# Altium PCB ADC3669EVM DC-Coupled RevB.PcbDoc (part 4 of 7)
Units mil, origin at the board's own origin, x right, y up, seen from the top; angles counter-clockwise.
Board outline 5000 x 2716.54 mil, 12 copper layers (Top Layer, L2 GND, L3 SIG, L4 GND, L5 PWR, L6 GND, L7 GND, L8 PWR, L9 GND, L10 PWR, L11 GND, Bottom Layer), stack 61 mil thick; 546 components, 341 nets, 2088 pads, 1256 vias.
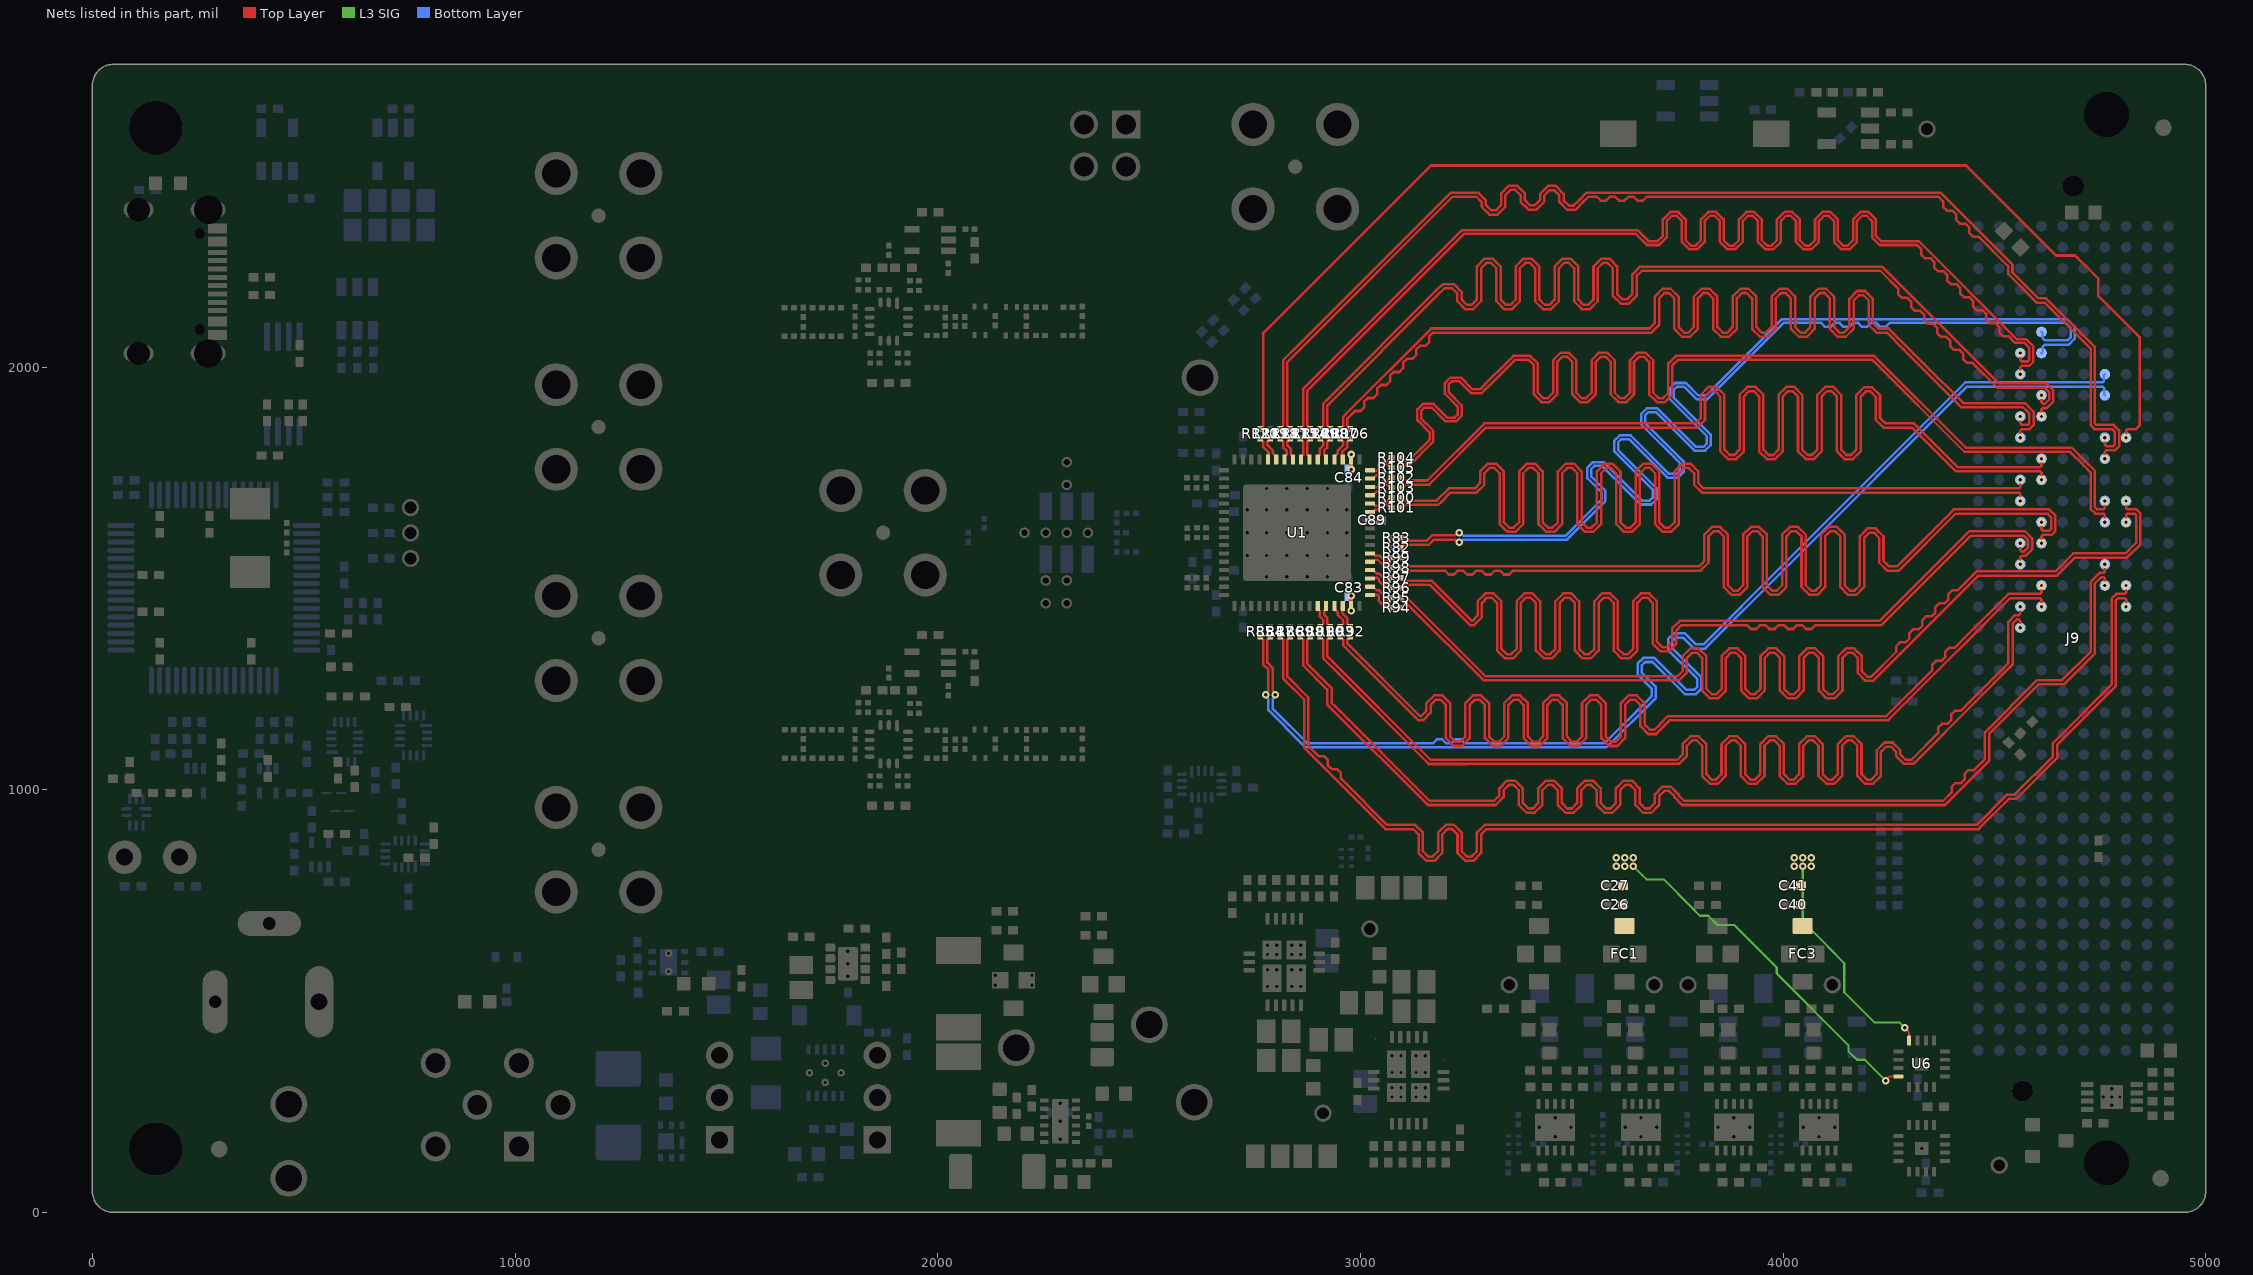
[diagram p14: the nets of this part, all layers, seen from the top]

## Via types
v1: diameter 18, hole 8, Top Layer to Bottom Layer, tented both sides, 1256 vias

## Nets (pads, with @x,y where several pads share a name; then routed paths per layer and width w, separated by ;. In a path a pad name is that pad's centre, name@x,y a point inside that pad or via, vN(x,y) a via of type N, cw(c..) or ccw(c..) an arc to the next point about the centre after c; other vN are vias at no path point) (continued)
DOUT3_n: R91.1 U1.43 | length 58.2
  Top Layer w6: U1.43@2899.21,1435.04 2899.21,1428.15 2904.06,1423.31 2904.06,1410.09 2912.06,1402.09 2912.06,1392.64 R91.1@2908.54,1389.13 ; R91.1@2905.21,1385.04 2905.21,1385.83 R91.1@2908.51,1389.13
DOUT3_p: R90.1 U1.44 | length 58.2
  Top Layer w6: U1.44@2918.9,1435.04 2918.9,1428.15 2914.06,1423.31 2914.06,1414.23 2922.06,1406.23 2922.06,1392.64 R90.1@2925.57,1389.13 ; R90.1@2925.6,1389.13 2928.9,1385.83 R90.1@2928.87,1385.04
DOUT4_n: R93.1 U1.45 | length 61.5
  Top Layer w6: U1.45@2938.58,1435.04 2938.58,1428.15 2946.81,1419.92 2946.81,1413.74 2959.43,1401.13 2959.43,1392.64 2955.91,1389.13 2952.58,1385.83 R93.1@2952.58,1385.04
DOUT4_p: R92.1 U1.46 | length 58.7
  Top Layer w6: U1.46@2958.27,1435.04 2956.81,1433.59 2956.81,1417.88 2969.43,1405.27 2969.43,1392.64 2972.94,1389.13 2976.27,1385.83 R92.1@2976.27,1385.04
DOUT5_n: R95.1 U1.50 | length 73.2
  Top Layer w6: U1.50@3023.23,1480.32 3030.12,1480.32 3038.62,1471.81 3044.26,1471.81 3053.63,1462.44 3053.63,1450.99 3057.14,1447.47 3065.63,1447.47 R95.1@3069.14,1450.99 ; R95.1@3069.14,1451.02 3072.44,1454.32 R95.1@3073.23,1454.32
DOUT5_p: R94.1 U1.49 | length 70.1
  Top Layer w6: U1.49@3023.23,1460.63 3024.41,1461.81 3040.11,1461.81 3043.63,1458.3 3043.63,1446.85 3053,1437.47 3065.63,1437.47 3069.14,1433.96 3072.44,1430.63 R94.1@3073.23,1430.63
DOUT6_n: R97.1 U1.52 | length 65.2
  Top Layer w6: U1.52@3023.23,1519.69 3030.12,1519.69 3038.62,1511.18 3044.26,1511.18 3053.63,1501.81 3053.63,1498.36 3057.14,1494.84 3065.63,1494.84 R97.1@3069.14,1498.36 ; R97.1@3069.14,1498.39 3072.44,1501.69 R97.1@3073.23,1501.69
DOUT6_p: R96.1 U1.51 | length 62.1
  Top Layer w6: U1.51@3023.23,1500 3024.41,1501.18 3040.11,1501.18 3043.63,1497.67 3043.63,1494.22 3053,1484.84 3065.63,1484.84 R96.1@3069.14,1481.33 ; R96.1@3069.14,1481.3 3072.44,1478 R96.1@3073.23,1478
DOUT7_n: R99.1 U1.54 | length 59.8
  Top Layer w6: U1.54@3023.23,1559.06 3030.12,1559.06 3034.96,1554.21 3045.14,1554.21 3057.14,1542.21 3065.63,1542.21 3069.14,1545.73 3072.44,1549.06 R99.1@3073.23,1549.06
DOUT7_p: R98.1 U1.53 | length 59.8
  Top Layer w6: U1.53@3023.23,1539.37 3030.12,1539.37 3034.96,1544.21 3041,1544.21 3053,1532.21 3065.63,1532.21 3069.14,1528.7 3072.44,1525.37 R98.1@3073.23,1525.37
DOUT8_n: R101.1 U1.59 | length 59.8
  Top Layer w6: U1.59@3023.23,1657.48 3030.12,1657.48 3034.96,1662.32 3045.14,1662.32 3057.14,1674.32 3065.63,1674.32 3069.14,1670.81 3072.44,1667.48 R101.1@3073.23,1667.48
DOUT8_p: R100.1 U1.60 | length 59.8
  Top Layer w6: U1.60@3023.23,1677.17 3030.12,1677.17 3034.96,1672.32 3041,1672.32 3053,1684.32 3065.63,1684.32 R100.1@3069.14,1687.84 ; R100.1@3069.14,1687.87 3072.44,1691.17 R100.1@3073.23,1691.17
DOUT9_n: R103.1 U1.61 | length 65.2
  Top Layer w6: U1.61@3023.23,1696.85 3030.12,1696.85 3038.62,1705.36 3044.26,1705.36 3053.63,1714.73 3053.63,1718.18 3057.14,1721.7 3065.63,1721.7 R103.1@3069.14,1718.18 ; R103.1@3069.14,1718.15 3072.44,1714.85 R103.1@3073.23,1714.85
DOUT9_p: R102.1 U1.62 | length 62.1
  Top Layer w6: U1.62@3023.23,1716.54 3024.41,1715.36 3040.11,1715.36 3043.63,1718.87 3043.63,1722.32 3053,1731.7 3065.63,1731.7 R102.1@3069.14,1735.21 ; R102.1@3069.14,1735.24 3072.44,1738.54 R102.1@3073.23,1738.54
DOUT10_n: R105.1 U1.63 | length 73.2
  Top Layer w6: U1.63@3023.23,1736.22 3030.12,1736.22 3038.62,1744.73 3044.26,1744.73 3053.63,1754.1 3053.63,1765.55 3057.14,1769.07 3065.63,1769.07 3069.14,1765.55 3072.44,1762.22 R105.1@3073.23,1762.22
DOUT10_p: R104.1 U1.64 | length 70.1
  Top Layer w6: U1.64@3023.23,1755.91 3024.41,1754.73 3040.11,1754.73 3043.63,1758.24 3043.63,1769.69 3053,1779.07 3065.63,1779.07 3069.14,1782.58 3072.44,1785.91 R104.1@3073.23,1785.91
DOUT11_n: R107.1 U1.4 | length 61.5
  Top Layer w6: U1.4@2938.58,1781.5 2938.58,1788.39 2946.81,1796.62 2946.81,1802.8 2959.43,1815.41 2959.43,1823.9 2955.91,1827.41 2952.58,1830.71 R107.1@2952.58,1831.5
DOUT11_p: R106.1 U1.3 | length 58.7
  Top Layer w6: U1.3@2958.27,1781.5 2956.81,1782.95 2956.81,1798.66 2969.43,1811.27 2969.43,1823.9 2972.94,1827.41 2976.27,1830.71 R106.1@2976.27,1831.5
DOUT12_n: R109.1 U1.6 | length 58.2
  Top Layer w6: U1.6@2899.21,1781.5 2899.21,1788.39 2904.06,1793.23 2904.06,1806.45 2912.06,1814.45 2912.06,1823.9 R109.1@2908.54,1827.41 ; R109.1@2905.21,1831.5 2905.21,1830.71 R109.1@2908.51,1827.41
DOUT12_p: R108.1 U1.5 | length 58.2
  Top Layer w6: U1.5@2918.9,1781.5 2918.9,1788.39 2914.06,1793.23 2914.06,1802.31 2922.06,1810.31 2922.06,1823.9 R108.1@2925.57,1827.41 ; R108.1@2925.6,1827.41 2928.9,1830.71 R108.1@2928.9,1831.5
DOUT13_n: R115.1 U1.8 | length 54.9
  Top Layer w6: R115.1@2857.84,1831.5 2857.84,1830.71 2861.14,1827.41 2864.69,1823.9 2864.69,1793.23 2859.84,1788.39 U1.8@2859.84,1781.5
DOUT13_p: R114.1 U1.7 | length 54.9
  Top Layer w6: R114.1@2878.2,1827.41 2874.69,1823.9 2874.69,1793.23 2879.53,1788.39 U1.7@2879.53,1781.5 ; R114.1@2878.23,1827.41 2881.53,1830.71 R114.1@2881.53,1831.5
DOUT14_n: R118.1 U1.10 | length 58.2
  Top Layer w6: R118.1@2810.47,1831.5 2810.47,1830.71 R118.1@2813.77,1827.41 ; R118.1@2813.8,1827.41 2817.32,1823.9 2817.32,1810.31 2825.32,1802.31 2825.32,1793.23 2820.47,1788.39 U1.10@2820.47,1781.5
DOUT14_p: R117.1 U1.9 | length 58.2
  Top Layer w6: R117.1@2834.16,1831.5 2834.16,1830.71 2830.86,1827.41 2827.32,1823.9 2827.32,1814.45 2835.32,1806.45 2835.32,1793.23 2840.16,1788.39 U1.9@2840.16,1781.5
DOUT15_n: R120.1 U1.12 | length 58.7
  Top Layer w6: R120.1@2763.1,1831.5 2763.1,1830.71 R120.1@2766.4,1827.41 ; R120.1@2766.43,1827.41 2769.95,1823.9 2769.95,1811.27 2782.56,1798.66 2782.56,1782.95 U1.12@2781.1,1781.5
DOUT15_p: R119.1 U1.11 | length 61.5
  Top Layer w6: R119.1@2783.46,1827.41 2779.95,1823.9 2779.95,1815.41 2792.56,1802.8 2792.56,1796.62 2800.79,1788.39 U1.11@2800.79,1781.5 ; R119.1@2783.49,1827.41 2786.79,1830.71 R119.1@2786.79,1831.5
DVDD12: C26.2 C27.2 C83.2 C84.2 FC1.3 U1.2 U1.47 U6.8 | length 929.9
  Top Layer w5: v1(4242.68,311.92) 4252.68,321.92 U6.8@4272.68,321.92
  Top Layer w9.5: v1(2977.95,1423.23) U1.47@2977.95,1435.04 v1(2977.95,1458.85) ; v1(2977.95,1757.69) U1.2@2977.95,1781.5 v1(2977.95,1793.31)
  L3 SIG w5: v1(3645.19,819.32) 3666.42,798.09 3667.04,798.09 3677.13,788 3717.75,788 3784.67,721.08 3784.67,720.51 3803.09,702.09 3822.96,702.09 3844.94,680.11 3884.38,680.11 3985,579.49 3985,565.36 4154.56,395.81 4154.56,381.68 4174.96,361.28 4193.32,361.28 v1(4242.68,311.92)
  other v1: 3605.19,819.32 3625.19,819.32 3605.19,839.32 3625.19,839.32 3645.19,839.32
DVDD18: C40.2 C41.2 C89.2 FC3.3 U1.58 U6.4 | length 575.5
  Top Layer w5: v1(4288.27,436.56) 4298.27,426.56 U6.4@4298.27,406.56
  Top Layer w9.5: U1.58@3023.23,1637.8 v1(3047.04,1637.8)
  L3 SIG w5: v1(4046.5,819.32) 4046.5,689.06 4105.49,630.06 4105.49,629.18 4144.8,589.87 4144.8,520.96 4216.05,449.72 4275.12,449.72 v1(4288.27,436.56)
  other v1: 4026.5,819.32 4066.5,819.32 4026.5,839.32 4046.5,839.32 4066.5,839.32
FMC_DCLK_n: J9.G7 R83.2 | length 2914
  Top Layer w6: R83.2@3095.28,1596.43 3096.06,1596.43 R83.2@3099.36,1593.13 ; R83.2@3099.36,1593.1 3102.88,1589.58 3157.53,1589.58 3169.89,1601.94 3223.99,1601.94 3230.49,1608.44 v1(3233.5,1608.44)
  Bottom Layer w6: v1(3233.5,1608.44) 3235.96,1608.44 3243.46,1600.94 3485.03,1600.94 3566.25,1682.16 3570.24,1686.15 3570.24,1703.97 3537.22,1736.99 3537.22,1762.27 3550.13,1775.17 3575.4,1775.17 3666.63,1683.95 3684.45,1683.95 3692.08,1691.59 3692.08,1709.4 3600.86,1800.63 3600.86,1825.91 3613.77,1838.81 3639.04,1838.81 3730.27,1747.59 3748.09,1747.59 3755.72,1755.22 3755.72,1773.04 3664.5,1864.27 3664.5,1889.54 3677.41,1902.45 3702.68,1902.45 3793.91,1811.23 3811.72,1811.23 3819.36,1818.86 3819.36,1836.68 3731.86,1924.19 3731.86,1949.46 3744.77,1962.37 3770.04,1962.37 3799.34,1933.07 3817.16,1933.07 3916.68,2032.59 3997.76,2113.67 4671.46,2113.67 4690.02,2095.11 4690.02,2067.27 4676.02,2053.27 4619.45,2053.27 4614.71,2048.52 4614.71,2036.56 J9.G7@4611.42,2033.27
FMC_DCLK_p: J9.G6 R82.2 | length 2914.2
  Top Layer w6: R82.2@3095.28,1572.74 3096.06,1572.74 R82.2@3099.36,1576.04 ; R82.2@3099.36,1576.07 3102.88,1579.58 3161.67,1579.58 3174.03,1591.94 3223.99,1591.94 3230.49,1585.44 v1(3233.5,1585.44)
  Bottom Layer w6: v1(3233.5,1585.44) 3236.52,1585.44 3243.02,1591.94 3488.76,1591.94 3572.62,1675.8 3579.24,1682.42 3579.24,1707.7 3546.22,1740.72 3546.22,1758.54 3553.85,1766.17 3571.67,1766.17 3662.9,1674.95 3688.17,1674.95 3701.08,1687.86 3701.08,1713.13 3609.86,1804.36 3609.86,1822.18 3617.49,1829.81 3635.31,1829.81 3726.54,1738.59 3751.81,1738.59 3764.72,1751.5 3764.72,1776.77 3673.5,1868 3673.5,1885.82 3681.13,1893.45 3698.95,1893.45 3790.18,1802.23 3815.45,1802.23 3828.36,1815.14 3828.36,1840.41 3740.86,1927.91 3740.86,1945.73 3748.49,1953.37 3766.31,1953.37 3795.61,1924.07 3820.89,1924.07 3923.04,2026.23 4001.49,2104.67 4090.33,2104.67 4099.64,2095.35 4112.09,2095.35 4121.4,2104.67 4133.85,2104.67 4143.17,2095.35 4155.61,2095.35 4164.93,2104.67 4177.38,2104.67 4186.69,2095.35 4199.14,2095.35 4208.45,2104.67 4220.9,2104.67 4230.22,2095.35 4242.66,2095.35 4251.98,2104.67 4667.73,2104.67 4681.02,2091.39 4681.02,2071 4673.29,2063.27 4619.45,2063.27 4614.71,2068.01 4614.71,2079.98 J9.G6@4611.42,2083.27
FMC_DOUT0_n: J9.D9 R85.2 | length 2922.8
  Top Layer w6: R85.2@2763.1,1362.99 2763.1,1362.21 R85.2@2766.4,1358.91 ; R85.2@2766.43,1358.91 2769.95,1355.39 2769.95,1296.6 2782.3,1284.24 2782.3,1234.28 2775.8,1227.78 v1(2775.8,1224.77)
  Bottom Layer w6: v1(2775.8,1224.77) 2775.8,1221.75 2782.3,1215.25 2782.3,1188.46 2863.3,1107.46 2870.61,1100.15 3028.89,1100.15 ; 3020.61,1100.15 3028.89,1100.15 ; J9.D9@4761.42,1933.27 4759.36,1935.33 4759.36,1950.15 4755.84,1953.67 4435.18,1953.67 4002.75,1521.25 3815.64,1334.13 3789.54,1334.13 3763.61,1360.07 3745.79,1360.07 3738.15,1352.43 3738.15,1334.61 3807.02,1265.74 3807.02,1239.63 3793.53,1226.14 3767.42,1226.14 3691.26,1302.3 3673.45,1302.3 3665.81,1294.66 3665.81,1276.84 3699.03,1243.62 3699.03,1217.52 3691.91,1210.4 3587.52,1106.01 3581.66,1100.15 3028.89,1100.15
FMC_DOUT0_p: J9.D8 R84.2 | length 2912.3
  Top Layer w6: R84.2@2783.46,1358.91 2779.95,1355.39 2779.95,1300.74 2792.3,1288.38 2792.3,1234.28 2798.8,1227.78 v1(2798.8,1224.77) ; R84.2@2783.49,1358.91 2786.79,1362.21 R84.2@2786.79,1362.99
  Bottom Layer w6: v1(2798.8,1224.77) 2798.8,1221.75 2792.3,1215.25 2792.3,1192.6 2874.75,1110.15 3014.41,1110.15 3128.3,1110.15 3171.83,1110.15 3181.14,1119.47 3193.59,1119.47 3202.9,1110.15 3215.35,1110.15 3224.67,1119.47 3237.11,1119.47 3246.43,1110.15 3577.51,1110.15 3684.83,1217.47 3689.03,1221.66 3689.03,1239.48 3655.81,1272.7 3655.81,1298.8 3669.3,1312.3 3695.41,1312.3 3771.57,1236.14 3789.38,1236.14 3797.02,1243.78 3797.02,1261.6 3728.15,1330.47 3728.15,1356.57 3741.64,1370.07 3767.75,1370.07 3793.68,1344.13 3811.5,1344.13 3995.68,1528.32 4431.03,1963.67 4755.44,1963.67 4758.96,1967.18 4758.96,1980.81 J9.D8@4761.42,1983.27
FMC_DOUT1_n: J9.C19 R87.2 | length 2951.2
  Top Layer w6: R87.2@2810.5,1362.99 2810.47,1362.21 R87.2@2813.77,1358.91 ; R87.2@2813.8,1358.91 2817.32,1355.39 2817.32,1263.61 2823.17,1257.75 2866.68,1214.25 2866.68,1099.6 2872.53,1093.74 3059.27,907 3073.16,907 3125.09,907 3137.69,894.4 3137.69,850.41 3156.15,831.95 3175.23,831.95 3193.69,850.41 3193.69,894.64 3206.29,907.24 3217.09,907.24 3229.69,894.64 3229.69,850.41 3248.15,831.95 3267.23,831.95 3285.69,850.41 3285.69,894.4 3298.29,907 3328.41,907 ; 3297.57,907 3328.41,907 ; v1(4811.42,1433.27) 4811.42,1449.75 4807.9,1453.27 4792.56,1453.27 4787.42,1448.12 4787.42,1245.13 4648.18,1105.89 4648.18,1074.89 4642.32,1069.04 4557.58,984.3 4551.73,978.44 4533.97,978.44 4462.52,907 3328.41,907
FMC_DOUT1_p: J9.C18 R86.2 | length 2919.3
  Top Layer w6: R86.2@2834.16,1362.99 2834.16,1362.21 2830.86,1358.91 2827.32,1355.39 2827.32,1267.75 2876.68,1218.39 2876.68,1103.74 2900.96,1079.46 2914.13,1079.46 2922.93,1070.65 2922.93,1057.48 2931.73,1048.68 2944.91,1048.68 2953.71,1039.88 2953.71,1026.7 2962.51,1017.9 3063.41,917 3073.16,917 3129.23,917 3147.69,898.54 3147.69,854.55 3160.29,841.95 3171.09,841.95 3183.69,854.55 3183.69,898.78 3202.15,917.24 3221.23,917.24 3239.69,898.78 3239.69,854.55 3252.29,841.95 3263.09,841.95 3275.69,854.55 3275.69,898.54 3294.15,917 3328.41,917 4458.38,917 4529.82,988.44 4547.58,988.44 4638.18,1079.04 4638.18,1110.03 4777.42,1249.27 4777.42,1452.26 4788.42,1463.27 4807.9,1463.27 4811.42,1466.78 v1(4811.42,1483.27)
FMC_DOUT2_n: J9.D18 R89.2 | length 2912.4
  Top Layer w6: R89.2@2857.87,1362.99 2857.9,1362.21 2861.2,1358.91 2864.74,1355.39 2864.74,1293.54 2922.06,1236.22 2922.06,1201.61 2924.98,1198.69 3159.67,964 3310.11,964 3320.18,964 3338.64,982.46 3338.64,998.86 3351.24,1011.46 3362.04,1011.46 3374.64,998.86 3374.64,964.18 3393.1,945.73 3412.18,945.73 3430.64,964.18 3430.64,998.86 3443.24,1011.46 3454.04,1011.46 3466.64,998.86 3466.64,964.18 3485.1,945.73 3504.18,945.73 3522.64,964.18 3522.64,998.86 3535.24,1011.46 3546.04,1011.46 3558.64,998.86 3558.64,964.18 3577.1,945.73 3596.18,945.73 3614.64,964.18 3614.64,998.86 3627.24,1011.46 3638.04,1011.46 3650.64,998.86 3650.64,964.18 3669.1,945.73 3688.18,945.73 3706.64,964.18 3706.64,984.98 3719.24,997.58 3730.04,997.58 3742.64,984.98 3742.64,982.46 3761.1,964 3808.97,964 4383.03,964 4487.42,1068.39 4487.42,1131.89 4604.79,1249.27 4664.55,1249.27 4670.41,1255.13 4731.56,1316.28 4737.42,1322.14 4737.42,1487.75 4752.93,1503.27 4757.9,1503.27 4761.42,1499.75 v1(4761.42,1483.27)
FMC_DOUT2_p: J9.D17 R88.2 | length 2911.3
  Top Layer w6: R88.2@2878.25,1358.91 2874.74,1355.39 2874.74,1297.68 2929.13,1243.29 2932.06,1240.36 2932.06,1205.76 2939.73,1198.09 3163.81,974 3310.11,974 3316.04,974 3328.64,986.6 3328.64,1003 3347.1,1021.46 3366.18,1021.46 3384.64,1003 3384.64,968.33 3397.24,955.73 3408.04,955.73 3420.64,968.33 3420.64,1003 3439.1,1021.46 3458.18,1021.46 3476.64,1003 3476.64,968.33 3489.24,955.73 3500.04,955.73 3512.64,968.33 3512.64,1003 3531.1,1021.46 3550.18,1021.46 3568.64,1003 3568.64,968.33 3581.24,955.73 3592.04,955.73 3604.64,968.33 3604.64,1003 3623.1,1021.46 3642.18,1021.46 3660.64,1003 3660.64,968.33 3673.24,955.73 3684.04,955.73 3696.64,968.33 3696.64,989.12 3715.1,1007.58 3734.18,1007.58 3752.64,989.12 3752.64,986.6 3765.24,974 3808.97,974 4378.89,974 4398.53,993.64 4398.53,1006.81 4407.33,1015.62 4420.5,1015.62 4429.3,1024.42 4429.3,1037.59 4438.1,1046.39 4451.28,1046.39 4477.42,1072.53 4477.42,1136.04 4600.65,1259.27 4660.41,1259.27 4727.42,1326.28 4727.42,1491.89 4748.79,1513.27 4757.9,1513.27 4761.42,1516.78 v1(4761.42,1533.27) ; R88.2@2878.28,1358.91 2881.58,1362.21 R88.2@2881.58,1362.99
FMC_DOUT3_n: J9.H20 R91.2 | length 2912.4
  Top Layer w6: R91.2@2905.21,1362.99 2905.21,1362.21 R91.2@2908.51,1358.91 ; R91.2@2908.54,1358.91 2912.06,1355.39 2912.06,1310.79 2948.93,1273.92 2949.06,1273.92 3158.99,1064 3161.89,1061.1 3161.99,1061 3250.59,1061 3250.68,1061.1 3744.02,1061.1 3754.03,1061.1 3772.43,1079.5 3772.43,1104.14 3785.03,1116.74 3795.83,1116.74 3808.43,1104.14 3808.43,1032.74 3826.83,1014.34 3845.83,1014.34 3864.23,1032.74 3864.23,1104.14 3876.83,1116.74 3887.63,1116.74 3900.23,1104.14 3900.23,1032.74 3918.63,1014.34 3937.64,1014.34 3956.04,1032.74 3956.04,1104.14 3968.64,1116.74 3979.44,1116.74 3992.04,1104.14 3992.04,1032.74 4010.44,1014.34 4029.44,1014.34 4047.84,1032.74 4047.84,1104.14 4060.44,1116.74 4071.24,1116.74 4083.84,1104.14 4083.84,1032.74 4102.25,1014.34 4121.25,1014.34 4139.65,1032.74 4139.65,1104.14 4152.25,1116.74 4163.05,1116.74 4175.65,1104.14 4175.65,1032.74 4194.05,1014.34 4213.05,1014.34 4231.46,1032.74 4231.46,1089.39 4244.06,1101.99 4254.86,1101.99 4267.46,1089.39 4267.46,1079.5 4285.86,1061.1 4296.93,1061.1 4307.96,1061.1 4310.69,1063.83 4310.83,1063.83 4455.86,1208.86 4537.14,1290.14 4543,1296 4543,1393.33 4552.93,1403.27 4557.9,1403.27 4561.42,1399.75 v1(4561.42,1383.27)
FMC_DOUT3_p: J9.H19 R90.2 | length 2924.7
  Top Layer w6: R90.2@2925.57,1358.91 2922.06,1355.39 2922.06,1314.94 3165.99,1071 3246.44,1071 3246.54,1071.1 3329.19,1071.1 3329.28,1071 ; R90.2@2925.6,1358.91 2928.9,1362.21 R90.2@2928.87,1362.99 ; 3315.99,1071 3329.28,1071 ; v1(4561.42,1433.27) 4561.42,1416.78 4557.9,1413.27 4548.79,1413.27 4533,1397.48 4533,1300.14 4419.51,1186.65 4406.33,1186.65 4397.53,1177.85 4397.53,1164.67 4388.73,1155.87 4375.56,1155.87 4366.76,1147.07 4366.76,1133.9 4303.86,1071 4296.93,1071 4289.96,1071 4277.36,1083.6 4277.36,1093.49 4258.96,1111.89 4239.95,1111.89 4221.55,1093.49 4221.55,1036.84 4208.95,1024.24 4198.15,1024.24 4185.55,1036.84 4185.55,1108.24 4167.15,1126.64 4148.15,1126.64 4129.75,1108.24 4129.75,1036.84 4117.15,1024.24 4106.35,1024.24 4093.75,1036.84 4093.75,1108.24 4075.35,1126.64 4056.34,1126.64 4037.94,1108.24 4037.94,1036.84 4025.34,1024.24 4014.54,1024.24 4001.94,1036.84 4001.94,1108.24 3983.54,1126.64 3964.54,1126.64 3946.14,1108.24 3946.14,1036.84 3933.54,1024.24 3922.74,1024.24 3910.14,1036.84 3910.14,1108.24 3891.74,1126.64 3872.73,1126.64 3854.33,1108.24 3854.33,1036.84 3841.73,1024.24 3830.93,1024.24 3818.33,1036.84 3818.33,1108.24 3799.93,1126.64 3780.93,1126.64 3762.52,1108.24 3762.52,1083.6 3749.93,1071 3744.02,1071 3329.28,1071
FMC_DOUT4_n: J9.G19 R93.2 | length 2912.4
  Top Layer w6: R93.2@2952.58,1362.99 2952.58,1362.21 2955.88,1358.91 2959.43,1355.39 2959.43,1341.75 2965.28,1335.89 3015.18,1286 3137.16,1164.02 3137.77,1164.02 3147.84,1164.02 3166.3,1182.48 3166.3,1200.83 3178.9,1213.43 3189.7,1213.43 3202.3,1200.83 3202.3,1122.02 3220.75,1103.56 3239.84,1103.56 3258.3,1122.02 3258.3,1200.83 3270.9,1213.43 3281.7,1213.43 3294.3,1200.83 3294.3,1122.02 3312.75,1103.56 3331.84,1103.56 3350.3,1122.02 3350.3,1200.83 3362.9,1213.43 3373.7,1213.43 3386.3,1200.83 3386.3,1122.02 3404.75,1103.56 3423.84,1103.56 3442.3,1122.02 3442.3,1200.83 3454.89,1213.43 3465.69,1213.43 3478.29,1200.83 3478.29,1122.02 3496.75,1103.56 3515.84,1103.56 3534.29,1122.02 3534.29,1200.83 3546.89,1213.43 3557.69,1213.43 3570.29,1200.83 3570.29,1122.02 3588.75,1103.56 3607.84,1103.56 3626.29,1122.02 3626.29,1200.83 3638.89,1213.43 3649.69,1213.43 3662.29,1200.83 3662.29,1150.47 3680.75,1132.01 3699.84,1132.01 3718.29,1150.47 3718.29,1151.42 3730.89,1164.02 3758.18,1164.02 4248.16,1164.02 4251.26,1167.12 4392,1307.86 4434,1349.86 4537.41,1453.27 4607.9,1453.27 4611.42,1449.75 v1(4611.42,1433.27)
FMC_DOUT4_p: J9.G18 R92.2 | length 2915
  Top Layer w6: R92.2@2976.27,1362.99 2976.27,1362.21 2972.97,1358.91 2969.43,1355.39 2969.43,1345.89 3137.77,1177.55 3141.3,1174.02 3143.7,1174.02 3156.3,1186.62 3156.3,1204.97 3174.75,1223.43 3193.84,1223.43 3212.3,1204.97 3212.3,1126.16 3224.9,1113.56 3235.7,1113.56 3248.3,1126.16 3248.3,1204.97 3266.75,1223.43 3285.84,1223.43 3304.3,1204.97 3304.3,1126.16 3316.9,1113.56 3327.7,1113.56 3340.3,1126.16 3340.3,1204.97 3358.75,1223.43 3377.84,1223.43 3396.3,1204.97 3396.3,1126.16 3408.9,1113.56 3419.7,1113.56 3432.3,1126.16 3432.3,1204.97 3450.75,1223.43 3469.84,1223.43 3488.29,1204.97 3488.29,1126.16 3500.89,1113.56 3511.69,1113.56 3524.29,1126.16 3524.29,1204.97 3542.75,1223.43 3561.84,1223.43 3580.29,1204.97 3580.29,1126.16 3592.89,1113.56 3603.69,1113.56 3616.29,1126.16 3616.29,1204.97 3634.75,1223.43 3653.84,1223.43 3672.29,1204.97 3672.29,1154.61 3684.89,1142.01 3695.69,1142.01 3708.29,1154.61 3708.29,1155.56 3726.75,1174.02 3758.18,1174.02 3761.72,1174.02 ; 3757.96,1174.02 3761.72,1174.02 ; v1(4611.42,1483.27) 4611.42,1466.78 4607.9,1463.27 4533.27,1463.27 4429.86,1359.86 4405.77,1335.77 4392.6,1335.77 4383.8,1326.97 4383.8,1313.8 4375,1305 4361.82,1305 4353.02,1296.2 4353.02,1283.02 4244.02,1174.02 3761.72,1174.02
FMC_DOUT5_n: J9.C15 R95.2 | length 2911
  Top Layer w6: R95.2@3095.28,1454.32 3096.06,1454.32 R95.2@3099.36,1451.02 ; R95.2@3099.36,1450.99 3102.88,1447.47 3116.68,1447.47 3295.48,1268.67 3744.07,1268.67 3750,1268.67 3762.6,1281.27 3762.6,1316.05 3781.06,1334.51 3800.14,1334.51 3818.6,1316.05 3818.6,1238.96 3831.2,1226.36 3842,1226.36 3854.6,1238.96 3854.6,1316.05 3873.06,1334.51 3892.14,1334.51 3910.6,1316.05 3910.6,1238.96 3923.2,1226.36 3934,1226.36 3946.6,1238.96 3946.6,1316.05 3965.06,1334.51 3984.14,1334.51 4002.6,1316.05 4002.6,1238.96 4015.2,1226.36 4026,1226.36 4038.6,1238.96 4038.6,1316.05 4057.06,1334.51 4076.14,1334.51 4094.6,1316.05 4094.6,1238.96 4107.2,1226.36 4118,1226.36 4130.6,1238.96 4130.6,1316.05 4149.06,1334.51 4168.14,1334.51 4186.6,1316.05 4186.6,1280.35 4199.2,1267.75 4206.35,1267.75 4208.96,1267.75 4267.81,1326.6 4267.81,1339.77 4276.61,1348.57 4289.79,1348.57 4298.59,1357.37 4298.59,1370.55 4307.39,1379.35 4320.56,1379.35 4329.36,1388.15 4329.36,1401.32 4338.17,1410.12 4351.34,1410.12 4360.14,1418.93 4360.14,1432.1 4368.94,1440.9 4382.12,1440.9 4390.92,1449.7 4390.92,1462.88 4399.72,1471.68 4412.89,1471.68 4452.14,1510.92 4458,1516.78 4644.04,1516.78 4686.52,1559.27 4810.05,1559.27 4835.23,1584.45 4835.23,1649.75 4831.71,1653.27 4814.93,1653.27 4811.42,1649.75 v1(4811.42,1633.27)
FMC_DOUT5_p: J9.C14 R94.2 | length 2905.5
  Top Layer w6: R94.2@3095.28,1430.63 3096.06,1430.63 3099.36,1433.93 3102.88,1437.47 3112.54,1437.47 3123.1,1426.92 3288.41,1261.6 3291.34,1258.67 3744.07,1258.67 3754.14,1258.67 3772.6,1277.13 3772.6,1311.91 3785.2,1324.51 3796,1324.51 3808.6,1311.91 3808.6,1234.82 3827.06,1216.36 3846.14,1216.36 3864.6,1234.82 3864.6,1311.91 3877.2,1324.51 3888,1324.51 3900.6,1311.91 3900.6,1234.82 3919.06,1216.36 3938.14,1216.36 3956.6,1234.82 3956.6,1311.91 3969.2,1324.51 3980,1324.51 3992.6,1311.91 3992.6,1234.82 4011.06,1216.36 4030.14,1216.36 4048.6,1234.82 4048.6,1311.91 4061.2,1324.51 4072,1324.51 4084.6,1311.91 4084.6,1234.82 4103.06,1216.36 4122.14,1216.36 4140.6,1234.82 4140.6,1311.91 4153.2,1324.51 4164,1324.51 4176.6,1311.91 4176.6,1276.21 4195.06,1257.75 4206.35,1257.75 4213.11,1257.75 4362.93,1407.57 4462.14,1506.78 4648.18,1506.78 4690.66,1549.27 4814.19,1549.27 4845.23,1580.31 4845.23,1653.89 4835.85,1663.27 4814.93,1663.27 4811.42,1666.78 v1(4811.42,1683.27)
FMC_DOUT6_n: J9.H17 R97.2 | length 2912.4
  Top Layer w6: R97.2@3095.28,1501.69 3096.06,1501.69 R97.2@3099.36,1498.39 ; R97.2@3099.36,1498.36 3102.88,1494.84 3168.44,1494.84 3214.48,1448.81 3258.87,1404.42 3263.54,1399.75 3264.8,1399.75 3277.4,1412.35 3277.4,1446.02 3295.86,1464.48 3314.94,1464.48 3333.4,1446.02 3333.4,1333.4 3346,1320.8 3356.8,1320.8 3369.4,1333.4 3369.4,1446.02 3387.86,1464.48 3406.94,1464.48 3425.4,1446.02 3425.4,1333.4 3438,1320.8 3448.8,1320.8 3461.4,1333.4 3461.4,1446.02 3479.86,1464.48 3498.94,1464.48 3517.4,1446.02 3517.4,1333.4 3530,1320.8 3540.8,1320.8 3553.4,1333.4 3553.4,1446.02 3571.86,1464.48 3590.94,1464.48 3609.4,1446.02 3609.4,1333.4 3622,1320.8 3632.8,1320.8 3645.4,1333.4 3645.4,1446.02 3663.86,1464.48 3682.94,1464.48 3701.4,1446.02 3701.4,1350.2 3714,1337.6 3724.8,1337.6 3737.4,1350.2 3737.4,1381.29 3755.86,1399.75 3860.69,1399.75 4228.44,1399.75 4434.1,1605.41 4439.95,1611.27 4573.02,1611.27 4589.42,1594.87 4589.42,1568.64 4574.05,1553.27 4564.93,1553.27 4561.42,1549.75 v1(4561.42,1533.27)
FMC_DOUT6_p: J9.H16 R96.2 | length 2910.2
  Top Layer w6: R96.2@3095.28,1478 3096.06,1478 R96.2@3099.36,1481.3 ; R96.2@3099.36,1481.33 3102.88,1484.84 3164.3,1484.84 3204.48,1444.67 3258.87,1390.28 3259.39,1389.75 3268.94,1389.75 3287.4,1408.21 3287.4,1441.88 3300,1454.48 3310.8,1454.48 3323.4,1441.88 3323.4,1329.26 3341.86,1310.8 3360.94,1310.8 3379.4,1329.26 3379.4,1441.88 3392,1454.48 3402.8,1454.48 3415.4,1441.88 3415.4,1329.26 3433.86,1310.8 3452.94,1310.8 3471.4,1329.26 3471.4,1441.88 3484,1454.48 3494.8,1454.48 3507.4,1441.88 3507.4,1329.26 3525.86,1310.8 3544.94,1310.8 3563.4,1329.26 3563.4,1441.88 3576,1454.48 3586.8,1454.48 3599.4,1441.88 3599.4,1329.26 3617.86,1310.8 3636.94,1310.8 3655.4,1329.26 3655.4,1441.88 3668,1454.48 3678.8,1454.48 3691.4,1441.88 3691.4,1346.06 3709.86,1327.6 3728.94,1327.6 3747.4,1346.06 3747.4,1377.15 3760,1389.75 3860.69,1389.75 3914.78,1389.75 3924.1,1380.44 3936.55,1380.44 3945.86,1389.75 3958.31,1389.75 3967.62,1380.44 3980.07,1380.44 3989.38,1389.75 4001.83,1389.75 4011.15,1380.44 4023.59,1380.44 4032.91,1389.75 4045.36,1389.75 4054.67,1380.44 4067.12,1380.44 4076.43,1389.75 4232.58,1389.75 4444.1,1601.27 4568.87,1601.27 4579.42,1590.72 4579.42,1572.78 4569.9,1563.27 4564.93,1563.27 4561.42,1566.78 v1(4561.42,1583.27)
FMC_DOUT7_n: J9.G16 R99.2 | length 2912.4
  Top Layer w6: R99.2@3095.28,1549.06 3096.06,1549.06 3099.36,1545.76 3116.42,1528.67 3795.05,1528.67 3800.98,1528.67 3813.58,1541.27 3813.58,1603.59 3832.04,1622.05 3851.12,1622.05 3869.58,1603.59 3869.58,1483.93 3882.18,1471.33 3892.98,1471.33 3905.58,1483.93 3905.58,1603.59 3924.04,1622.05 3943.12,1622.05 3961.58,1603.59 3961.58,1483.93 3974.18,1471.33 3984.98,1471.33 3997.58,1483.93 3997.58,1603.59 4016.04,1622.05 4035.12,1622.05 4053.58,1603.59 4053.58,1483.93 4066.18,1471.33 4076.98,1471.33 4089.58,1483.93 4089.58,1603.59 4108.04,1622.05 4127.12,1622.05 4145.58,1603.59 4145.58,1483.93 4158.18,1471.33 4168.98,1471.33 4181.58,1483.93 4181.58,1599.78 4200.04,1618.23 4219.12,1618.23 4237.58,1599.78 4237.58,1541.27 4250.18,1528.67 4269.79,1528.67 4398.53,1657.41 4404.38,1663.27 4629.48,1663.27 4644,1648.74 4644,1612.64 4634.63,1603.27 4614.93,1603.27 4611.42,1599.75 v1(4611.42,1583.27)
FMC_DOUT7_p: J9.G15 R98.2 | length 2904.5
  Top Layer w6: R98.2@3095.28,1525.37 3096.3,1524.34 3106.61,1524.34 3112.28,1518.67 3199.66,1518.67 3208.97,1509.36 3221.42,1509.36 3230.73,1518.67 3243.18,1518.67 3252.49,1509.36 3264.94,1509.36 3274.26,1518.67 3286.7,1518.67 3296.02,1509.36 3308.47,1509.36 3317.78,1518.67 3330.23,1518.67 3339.54,1509.36 3351.99,1509.36 3361.31,1518.67 3795.05,1518.67 3805.12,1518.67 3823.58,1537.13 3823.58,1599.45 3836.18,1612.05 3846.98,1612.05 3859.58,1599.45 3859.58,1479.78 3878.04,1461.33 3897.12,1461.33 3915.58,1479.78 3915.58,1599.45 3928.18,1612.05 3938.98,1612.05 3951.58,1599.45 3951.58,1479.78 3970.04,1461.33 3989.12,1461.33 4007.58,1479.78 4007.58,1599.45 4020.18,1612.05 4030.98,1612.05 4043.58,1599.45 4043.58,1479.78 4062.04,1461.33 4081.12,1461.33 4099.58,1479.78 4099.58,1599.45 4112.18,1612.05 4122.98,1612.05 4135.58,1599.45 4135.58,1479.78 4154.04,1461.33 4173.12,1461.33 4191.58,1479.78 4191.58,1595.63 4204.18,1608.23 4214.98,1608.23 4227.58,1595.63 4227.58,1537.13 4246.04,1518.67 4269.79,1518.67 4273.93,1518.67 4408.53,1653.27 4625.33,1653.27 4634,1644.6 4634,1616.78 4630.49,1613.27 4614.93,1613.27 4611.42,1616.78 v1(4611.42,1633.27)
FMC_DOUT8_n: J9.H14 R101.2 | length 2911.4
  Top Layer w6: R101.2@3095.28,1667.48 3096.06,1667.48 3099.36,1670.78 3102.88,1674.32 3184.51,1674.32 3190.37,1680.18 3213.45,1703.27 3264.8,1703.27 3274.87,1703.27 3293.33,1721.73 3293.33,1748.92 3305.93,1761.52 3316.73,1761.52 3329.33,1748.92 3329.33,1628.55 3347.79,1610.09 3366.87,1610.09 3385.33,1628.55 3385.33,1748.92 3397.93,1761.52 3408.73,1761.52 3421.33,1748.92 3421.33,1628.55 3439.79,1610.09 3458.87,1610.09 3477.33,1628.55 3477.33,1748.92 3489.93,1761.52 3500.73,1761.52 3513.33,1748.92 3513.33,1628.55 3531.79,1610.09 3550.87,1610.09 3569.33,1628.55 3569.33,1748.92 3581.93,1761.52 3592.73,1761.52 3605.33,1748.92 3605.33,1628.55 3623.79,1610.09 3642.87,1610.09 3661.33,1628.55 3661.33,1748.92 3673.93,1761.52 3684.73,1761.52 3697.33,1748.92 3697.33,1628.55 3715.79,1610.09 3734.87,1610.09 3753.33,1628.55 3753.33,1748.92 3765.93,1761.52 3776.73,1761.52 3789.33,1748.92 3789.33,1721.73 3807.79,1703.27 3887.63,1703.27 4557.9,1703.27 4561.42,1699.75 v1(4561.42,1683.27)
FMC_DOUT8_p: J9.H13 R100.2 | length 2911.4
  Top Layer w6: R100.2@3095.28,1691.17 3096.06,1691.17 R100.2@3099.36,1687.87 ; R100.2@3099.36,1687.84 3102.88,1684.32 3180.37,1684.32 3209.31,1713.27 3264.8,1713.27 3270.73,1713.27 3283.33,1725.87 3283.33,1753.06 3301.79,1771.52 3320.87,1771.52 3339.33,1753.06 3339.33,1632.69 3351.93,1620.09 3362.73,1620.09 3375.33,1632.69 3375.33,1753.06 3393.79,1771.52 3412.87,1771.52 3431.33,1753.06 3431.33,1632.69 3443.93,1620.09 3454.73,1620.09 3467.33,1632.69 3467.33,1753.06 3485.79,1771.52 3504.87,1771.52 3523.33,1753.06 3523.33,1632.69 3535.93,1620.09 3546.73,1620.09 3559.33,1632.69 3559.33,1753.06 3577.79,1771.52 3596.87,1771.52 3615.33,1753.06 3615.33,1632.69 3627.93,1620.09 3638.73,1620.09 3651.33,1632.69 3651.33,1753.06 3669.79,1771.52 3688.87,1771.52 3707.33,1753.06 3707.33,1632.69 3719.93,1620.09 3730.73,1620.09 3743.33,1632.69 3743.33,1753.06 3761.79,1771.52 3780.87,1771.52 3799.33,1753.06 3799.33,1725.87 3811.93,1713.27 3887.63,1713.27 4557.9,1713.27 4561.42,1716.78 v1(4561.42,1733.27)
FMC_DOUT9_n: J9.G13 R103.2 | length 2912.2
  Top Layer w6: R103.2@3095.28,1714.85 3102.12,1721.7 3162.26,1721.7 3168.12,1727.55 3297.35,1856.78 3786.76,1856.78 3796.83,1856.78 3815.29,1875.24 3815.29,1930.4 3827.89,1943 3838.69,1943 3851.29,1930.4 3851.29,1800.56 3869.74,1782.1 3888.83,1782.1 3907.29,1800.56 3907.29,1930.4 3919.89,1943 3930.69,1943 3943.29,1930.4 3943.29,1800.56 3961.74,1782.1 3980.83,1782.1 3999.29,1800.56 3999.29,1930.4 4011.89,1943 4022.69,1943 4035.29,1930.4 4035.29,1800.56 4053.74,1782.1 4072.83,1782.1 4091.29,1800.56 4091.29,1930.4 4103.89,1943 4114.69,1943 4127.29,1930.4 4127.29,1800.56 4145.74,1782.1 4164.83,1782.1 4183.29,1800.56 4183.29,1929.78 4195.89,1942.38 4206.69,1942.38 4219.29,1929.78 4219.29,1875.24 4237.74,1856.78 4295.44,1856.78 4305.19,1856.78 4402.85,1759.13 4408.71,1753.27 4607.9,1753.27 4611.42,1749.75 v1(4611.42,1733.27)
FMC_DOUT9_p: J9.G12 R102.2 | length 2912.2
  Top Layer w6: R102.2@3095.28,1738.54 3102.12,1731.7 3158.12,1731.7 3293.21,1866.78 3786.76,1866.78 3792.69,1866.78 3805.29,1879.38 3805.29,1934.54 3823.74,1953 3842.83,1953 3861.29,1934.54 3861.29,1804.7 3873.89,1792.1 3884.69,1792.1 3897.29,1804.7 3897.29,1934.54 3915.74,1953 3934.83,1953 3953.29,1934.54 3953.29,1804.7 3965.89,1792.1 3976.69,1792.1 3989.29,1804.7 3989.29,1934.54 4007.74,1953 4026.83,1953 4045.29,1934.54 4045.29,1804.7 4057.89,1792.1 4068.69,1792.1 4081.29,1804.7 4081.29,1934.54 4099.74,1953 4118.83,1953 4137.29,1934.54 4137.29,1804.7 4149.89,1792.1 4160.69,1792.1 4173.29,1804.7 4173.29,1933.92 4191.74,1952.38 4210.83,1952.38 4229.29,1933.92 4229.29,1879.38 4241.89,1866.78 4295.44,1866.78 4309.34,1866.78 4412.85,1763.27 4607.9,1763.27 4611.42,1766.78 v1(4611.42,1783.27)
FMC_DOUT10_n: J9.D15 R105.2 | length 2912.7
  Top Layer w6: R105.2@3095.28,1762.22 3096.06,1762.22 3099.36,1765.52 3102.88,1769.07 3103.5,1769.07 3104,1769.57 3118.09,1769.57 3166.06,1817.53 3172.68,1824.15 3172.68,1849.43 3143.79,1878.32 3143.79,1896.14 3151.43,1903.78 3169.25,1903.78 3201.5,1871.52 3226.77,1871.52 3239.68,1884.43 3239.68,1909.71 3208.65,1940.74 3208.65,1958.56 3216.29,1966.2 3234.11,1966.2 3261.78,1938.52 3287.05,1938.52 3296.23,1947.7 3296.58,1947.7 3303.19,1954.31 3303.19,1954.57 3303.1,1954.57 3346.42,1997.9 3365.79,2017.27 3397.71,2017.27 3410.31,2004.67 3410.31,1935.43 3428.47,1917.27 3447.14,1917.27 3465.31,1935.43 3465.31,2012.25 3477.91,2024.85 3488.71,2024.85 3501.31,2012.25 3501.31,1935.43 3519.47,1917.27 3538.14,1917.27 3556.31,1935.43 3556.31,2012.25 3568.91,2024.85 3579.71,2024.85 3592.31,2012.25 3592.31,1935.43 3610.47,1917.27 3629.14,1917.27 3647.31,1935.43 3647.31,2012.25 3659.91,2024.85 3670.71,2024.85 3683.31,2012.25 3683.31,1935.43 3701.47,1917.27 3720.14,1917.27 3738.31,1935.43 3738.31,2004.67 3750.91,2017.27 3805.12,2017.27 4211.14,2017.27 4428.64,1799.77 4431.37,1799.77 4431.87,1799.27 4678.93,1799.27 4711.42,1766.78 4727.42,1750.78 4727.42,1664.59 4738.75,1653.27 4757.9,1653.27 4761.42,1649.75 v1(4761.42,1633.27)
FMC_DOUT10_p: J9.D14 R104.2 | length 2912.7
  Top Layer w6: R104.2@3095.28,1785.91 3096.06,1785.91 3099.36,1782.61 3102.88,1779.07 3103.5,1779.07 3104,1778.57 3114.36,1778.57 3159.7,1823.9 3163.68,1827.88 3163.68,1845.7 3134.79,1874.59 3134.79,1899.87 3147.7,1912.78 3172.97,1912.78 3205.23,1880.52 3223.05,1880.52 3230.68,1888.16 3230.68,1905.98 3199.65,1937.01 3199.65,1962.29 3212.56,1975.2 3237.83,1975.2 3265.5,1947.52 3283.32,1947.52 3289.87,1954.07 3289.87,1954.42 3293.69,1958.24 3293.69,1958.6 3296.38,1961.29 3346.42,2011.33 3361.86,2026.77 3401.64,2026.77 3419.81,2008.6 3419.81,1939.37 3432.41,1926.77 3443.21,1926.77 3455.81,1939.37 3455.81,2016.19 3473.97,2034.35 3492.64,2034.35 3510.81,2016.19 3510.81,1939.37 3523.41,1926.77 3534.21,1926.77 3546.81,1939.37 3546.81,2016.19 3564.97,2034.35 3583.64,2034.35 3601.81,2016.19 3601.81,1939.37 3614.41,1926.77 3625.21,1926.77 3637.81,1939.37 3637.81,2016.19 3655.97,2034.35 3674.64,2034.35 3692.81,2016.19 3692.81,1939.37 3705.41,1926.77 3716.21,1926.77 3728.81,1939.37 3728.81,2008.6 3746.97,2026.77 3805.12,2026.77 4215.08,2026.77 4432.58,1809.27 4683.07,1809.27 4715.56,1776.78 4737.42,1754.92 4737.42,1668.74 4742.89,1663.27 4757.9,1663.27 4761.42,1666.78 v1(4761.42,1683.27)
FMC_DOUT11_n: J9.H11 R107.2 | length 2912.4
  Top Layer w6: R107.2@2952.58,1853.55 2952.58,1854.33 2955.88,1857.63 2959.43,1861.15 2959.43,1882.95 2965.28,1888.81 3167.86,2091.39 3678.14,2091.39 3684.07,2091.39 3696.67,2103.99 3696.67,2166.86 3715.12,2185.32 3734.21,2185.32 3752.67,2166.86 3752.67,2094.4 3765.27,2081.8 3776.07,2081.8 3788.67,2094.4 3788.67,2166.86 3807.12,2185.32 3826.21,2185.32 3844.67,2166.86 3844.67,2094.4 3857.27,2081.8 3868.07,2081.8 3880.67,2094.4 3880.67,2166.86 3899.12,2185.32 3918.21,2185.32 3936.67,2166.86 3936.67,2094.4 3949.27,2081.8 3960.07,2081.8 3972.67,2094.4 3972.67,2166.86 3991.12,2185.32 4010.21,2185.32 4028.67,2166.86 4028.67,2094.4 4041.27,2081.8 4052.07,2081.8 4064.67,2094.4 4064.67,2166.86 4083.12,2185.32 4102.21,2185.32 4120.67,2166.86 4120.67,2094.4 4133.27,2081.8 4144.07,2081.8 4156.67,2094.4 4156.67,2161.62 4175.12,2180.07 4194.21,2180.07 4212.67,2161.62 4212.67,2103.99 4225.27,2091.39 4234.39,2091.39 4249.67,2091.39 4333.64,2007.41 4426.37,1914.68 4572.32,1914.68 4592.63,1894.37 4592.63,1862.64 4583.25,1853.27 4564.93,1853.27 4561.42,1849.75 v1(4561.42,1833.27)
FMC_DOUT11_p: J9.H10 R106.2 | length 2909
  Top Layer w6: R106.2@2976.27,1853.55 2976.27,1854.33 2972.97,1857.63 2969.43,1861.15 2969.43,1878.81 2986.76,1896.14 2999.94,1896.14 3008.74,1904.94 3008.74,1918.12 3017.54,1926.92 3030.71,1926.92 3039.51,1935.72 3039.51,1948.89 3048.31,1957.69 3061.49,1957.69 3070.29,1966.49 3070.29,1979.67 3079.09,1988.47 3092.26,1988.47 3101.07,1997.27 3101.07,2010.44 3109.87,2019.25 3123.04,2019.25 3131.84,2028.05 3131.84,2041.22 3140.64,2050.02 3153.82,2050.02 3162.62,2058.82 3162.62,2072 3172.01,2081.39 3678.14,2081.39 3688.21,2081.39 3706.67,2099.84 3706.67,2162.72 3719.27,2175.32 3730.07,2175.32 3742.67,2162.72 3742.67,2090.26 3761.12,2071.8 3780.21,2071.8 3798.67,2090.26 3798.67,2162.72 3811.27,2175.32 3822.07,2175.32 3834.67,2162.72 3834.67,2090.26 3853.12,2071.8 3872.21,2071.8 3890.67,2090.26 3890.67,2162.72 3903.27,2175.32 3914.07,2175.32 3926.67,2162.72 3926.67,2090.26 3945.12,2071.8 3964.21,2071.8 3982.67,2090.26 3982.67,2162.72 3995.27,2175.32 4006.07,2175.32 4018.67,2162.72 4018.67,2090.26 4037.12,2071.8 4056.21,2071.8 4074.67,2090.26 4074.67,2162.72 4087.27,2175.32 4098.07,2175.32 4110.67,2162.72 4110.67,2090.26 4129.12,2071.8 4148.21,2071.8 4166.67,2090.26 4166.67,2157.47 4179.27,2170.07 4190.07,2170.07 4202.67,2157.47 4202.67,2099.84 4221.12,2081.39 4234.39,2081.39 4245.53,2081.39 4284.96,2041.95 4422.23,1904.68 4568.18,1904.68 4576.66,1896.2 4582.63,1890.23 4582.63,1866.78 4579.11,1863.27 4564.93,1863.27 4561.42,1866.78 v1(4561.42,1883.27)
FMC_DOUT12_n: J9.G10 R109.2 | length 2911.6
  Top Layer w6: R109.2@2905.21,1854.33 R109.2@2908.51,1857.63 ; R109.2@2908.54,1857.63 2912.06,1861.15 2912.06,1913.67 2919.37,1920.98 3180.5,2182.12 3194.94,2196.56 3221.05,2196.56 3239.5,2178.1 3239.5,2159.99 3252.1,2147.39 3262.9,2147.39 3275.5,2159.99 3275.5,2238.04 3293.96,2256.5 3313.05,2256.5 3331.5,2238.04 3331.5,2159.99 3344.1,2147.39 3354.9,2147.39 3367.5,2159.99 3367.5,2238.04 3385.96,2256.5 3405.05,2256.5 3423.5,2238.04 3423.5,2159.99 3436.1,2147.39 3446.9,2147.39 3459.5,2159.99 3459.5,2238.04 3477.96,2256.5 3497.05,2256.5 3515.5,2238.04 3515.5,2159.99 3528.1,2147.39 3538.9,2147.39 3551.5,2159.99 3551.5,2238.04 3569.96,2256.5 3589.05,2256.5 3607.5,2238.04 3607.5,2172.85 3620.1,2160.25 3630.9,2160.25 3643.5,2172.85 3643.5,2219.51 3661.96,2237.97 3725.08,2237.97 4234.09,2237.97 4510.79,1961.27 4623.02,1961.27 4639.42,1944.87 4639.42,1918.64 4624.05,1903.27 4614.93,1903.27 4611.42,1899.75 v1(4611.42,1883.27)
FMC_DOUT12_p: J9.G9 R108.2 | length 2909
  Top Layer w6: R108.2@2925.57,1857.63 2922.06,1861.15 2922.06,1909.53 3180.5,2167.98 3199.09,2186.56 3216.9,2186.56 3229.5,2173.96 3229.5,2155.85 3247.96,2137.39 3267.05,2137.39 3285.5,2155.85 3285.5,2233.9 3298.1,2246.5 3308.9,2246.5 3321.5,2233.9 3321.5,2155.85 3339.96,2137.39 3359.05,2137.39 3377.5,2155.85 3377.5,2233.9 3390.1,2246.5 3400.9,2246.5 3413.5,2233.9 3413.5,2155.85 3431.96,2137.39 3451.05,2137.39 3469.5,2155.85 3469.5,2233.9 3482.1,2246.5 3492.9,2246.5 3505.5,2233.9 3505.5,2155.85 3523.96,2137.39 3543.05,2137.39 3561.5,2155.85 3561.5,2233.9 3574.1,2246.5 3584.9,2246.5 3597.5,2233.9 3597.5,2168.71 3615.96,2150.25 3635.05,2150.25 3653.5,2168.71 3653.5,2215.37 3666.1,2227.97 3725.08,2227.97 4229.95,2227.97 4272.1,2185.81 4272.1,2172.64 4280.91,2163.84 4294.08,2163.84 4302.88,2155.03 4302.88,2141.86 4311.68,2133.06 4324.86,2133.06 4333.66,2124.26 4333.66,2111.09 4342.46,2102.28 4355.63,2102.28 4364.43,2093.48 4364.43,2080.31 4373.23,2071.51 4386.41,2071.51 4395.21,2062.71 4395.21,2049.53 4404.01,2040.73 4417.18,2040.73 4425.99,2031.93 4425.99,2018.76 4434.79,2009.95 4447.96,2009.95 4506.65,1951.27 4618.87,1951.27 4629.42,1940.72 4629.42,1922.78 4619.9,1913.27 4614.93,1913.27 4611.42,1916.78 v1(4611.42,1933.27) ; R108.2@2925.6,1857.63 2928.9,1854.33 R108.2@2928.9,1853.55
FMC_DOUT13_n: J9.H8 R115.2 | length 2903.6
  Top Layer w6: R115.2@2857.84,1853.55 2857.84,1854.33 2861.14,1857.63 2864.69,1861.15 2864.69,1948.69 2870.54,1954.54 2933.27,2017.27 2979.27,2063.27 3240,2324 3655.24,2324 3681.32,2297.92 3697.33,2297.92 3702.97,2297.92 3715.57,2310.52 3715.57,2349.22 3733.44,2367.09 3751.69,2367.09 3769.57,2349.22 3769.57,2300.08 3782.17,2287.48 3792.97,2287.48 3805.57,2300.08 3805.57,2349.22 3823.44,2367.09 3841.69,2367.09 3859.57,2349.22 3859.57,2300.08 3872.17,2287.48 3882.97,2287.48 3895.57,2300.08 3895.57,2349.22 3913.44,2367.09 3931.69,2367.09 3949.57,2349.22 3949.57,2300.08 3962.17,2287.48 3972.97,2287.48 3985.57,2300.08 3985.57,2349.22 4003.44,2367.09 4021.69,2367.09 4039.57,2349.22 4039.57,2300.08 4052.17,2287.48 4062.97,2287.48 4075.57,2300.08 4075.57,2349.22 4093.44,2367.09 4111.69,2367.09 4129.57,2349.22 4129.57,2300.08 4142.17,2287.48 4152.97,2287.48 4165.57,2300.08 4165.57,2349.22 4183.44,2367.09 4201.69,2367.09 4219.57,2349.22 4219.57,2310.52 4232.17,2297.92 4304.41,2297.92 4320.98,2297.92 4552.63,2066.27 4574.73,2066.27 4592,2049 4592,2012.64 4582.63,2003.27 4564.93,2003.27 4561.42,1999.75 v1(4561.42,1983.27)
FMC_DOUT13_p: J9.H7 R114.2 | length 2909.6
  Top Layer w6: R114.2@2878.2,1857.63 2874.69,1861.15 2874.69,1944.54 3245.14,2315 3651.51,2315 3677.59,2288.92 3697.33,2288.92 3706.69,2288.92 3724.57,2306.79 3724.57,2345.49 3737.17,2358.09 3747.97,2358.09 3760.57,2345.49 3760.57,2296.35 3778.44,2278.48 3796.69,2278.48 3814.57,2296.35 3814.57,2345.49 3827.17,2358.09 3837.97,2358.09 3850.57,2345.49 3850.57,2296.35 3868.44,2278.48 3886.69,2278.48 3904.57,2296.35 3904.57,2345.49 3917.17,2358.09 3927.97,2358.09 3940.57,2345.49 3940.57,2296.35 3958.44,2278.48 3976.69,2278.48 3994.57,2296.35 3994.57,2345.49 4007.17,2358.09 4017.97,2358.09 4030.57,2345.49 4030.57,2296.35 4048.44,2278.48 4066.69,2278.48 4084.57,2296.35 4084.57,2345.49 4097.17,2358.09 4107.97,2358.09 4120.57,2345.49 4120.57,2296.35 4138.44,2278.48 4156.69,2278.48 4174.57,2296.35 4174.57,2345.49 4187.17,2358.09 4197.97,2358.09 4210.57,2345.49 4210.57,2306.79 4228.44,2288.92 4304.41,2288.92 4317.26,2288.92 4326.41,2279.76 4326.41,2266.59 4335.21,2257.79 4348.39,2257.79 4357.19,2248.99 4357.19,2235.81 4365.99,2227.01 4379.16,2227.01 4387.96,2218.21 4387.96,2205.04 4396.77,2196.23 4409.94,2196.23 4418.74,2187.43 4418.74,2174.26 4427.54,2165.46 4440.72,2165.46 4449.52,2156.66 4449.52,2143.48 4458.32,2134.68 4471.49,2134.68 4480.29,2125.88 4480.29,2112.71 4489.09,2103.91 4502.27,2103.91 4511.07,2095.1 4511.07,2081.93 4519.87,2073.13 4533.04,2073.13 4548.91,2057.27 4571,2057.27 4582,2046.27 4582,2016.78 4578.49,2013.27 4564.93,2013.27 4561.42,2016.78 v1(4561.42,2033.27) ; R114.2@2878.23,1857.63 2881.53,1854.33 R114.2@2881.53,1853.55
FMC_DOUT14_n: J9.D12 R118.2 | length 2912.4
  Top Layer w6: R118.2@2810.47,1853.55 2810.47,1854.33 R118.2@2813.77,1857.63 ; R118.2@2813.8,1857.63 2817.32,1861.15 2817.32,2016.18 2856.28,2055.14 3214.13,2413 3222.43,2413 3278.51,2413 3296.96,2394.54 3296.96,2383.57 3309.56,2370.97 3320.36,2370.97 3332.96,2383.57 3332.96,2411.01 3351.42,2429.47 3370.51,2429.47 3388.96,2411.01 3388.96,2395.12 3401.56,2382.52 3412.36,2382.52 3424.96,2395.12 3424.96,2410.07 3443.42,2428.53 3462.51,2428.53 3480.96,2410.07 3480.96,2394.54 3493.56,2381.94 3504.36,2381.94 3516.96,2394.54 3535.42,2413 3549.35,2413 4372.13,2413 4542.8,2242.33 4542.8,2224.02 4604.02,2162.8 4622.33,2162.8 4731.56,2053.57 4737.42,2047.71 4737.42,1866.78 4740.93,1863.27 4782.11,1863.27 4795,1850.38 4795,1812.64 4791.48,1809.13 4785.63,1803.27 4764.93,1803.27 4761.42,1799.75 v1(4761.42,1783.27)
FMC_DOUT14_p: J9.D11 R117.2 | length 2909
  Top Layer w6: R117.2@2834.16,1853.55 2834.16,1854.33 2830.86,1857.63 2827.32,1861.15 2827.32,2012.04 2866.28,2051 2872.76,2057.49 3218.28,2403 3222.43,2403 3274.36,2403 3286.96,2390.4 3286.96,2379.43 3305.42,2360.97 3324.51,2360.97 3342.96,2379.43 3342.96,2406.87 3355.56,2419.47 3366.36,2419.47 3378.96,2406.87 3378.96,2390.97 3397.42,2372.52 3416.51,2372.52 3434.96,2390.97 3434.96,2405.93 3447.56,2418.53 3458.36,2418.53 3470.96,2405.93 3470.96,2390.4 3489.42,2371.94 3508.51,2371.94 3526.96,2390.4 3539.56,2403 3549.35,2403 3559.33,2403 3568.64,2393.68 3581.09,2393.68 3590.41,2403 3602.85,2403 3612.17,2393.68 3624.62,2393.68 3633.93,2403 3646.38,2403 3655.69,2393.68 3668.14,2393.68 3677.45,2403 4367.99,2403 4378.87,2392.12 4378.87,2378.94 4387.67,2370.14 4400.84,2370.14 4409.65,2361.34 4409.65,2348.17 4418.45,2339.37 4431.62,2339.37 4440.42,2330.56 4440.42,2317.39 4449.22,2308.59 4462.4,2308.59 4532.75,2238.24 4532.75,2219.93 4599.88,2152.8 4618.19,2152.8 4727.42,2043.57 4727.42,1862.64 4736.79,1853.27 4777.97,1853.27 4785,1846.24 4785,1816.78 4781.48,1813.27 4764.93,1813.27 4761.42,1816.78 v1(4761.42,1833.27)
FMC_DOUT15_n: J9.C11 R120.2 | length 2922.6
  Top Layer w6: R120.2@2763.1,1853.55 2763.1,1854.33 2766.4,1857.63 2766.93,1857.63 2770.45,1861.15 2770.45,2080.77 3166.67,2477 4433.14,2477 4646.07,2264.07 4690.86,2264.07 4696.72,2258.21 4740.01,2214.92 4745.87,2209.06 4745.87,2168.24 4838.14,2075.97 4844,2070.11 4844,1862.64 4834.63,1853.27 4814.93,1853.27 4811.42,1849.75 v1(4811.42,1833.27)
